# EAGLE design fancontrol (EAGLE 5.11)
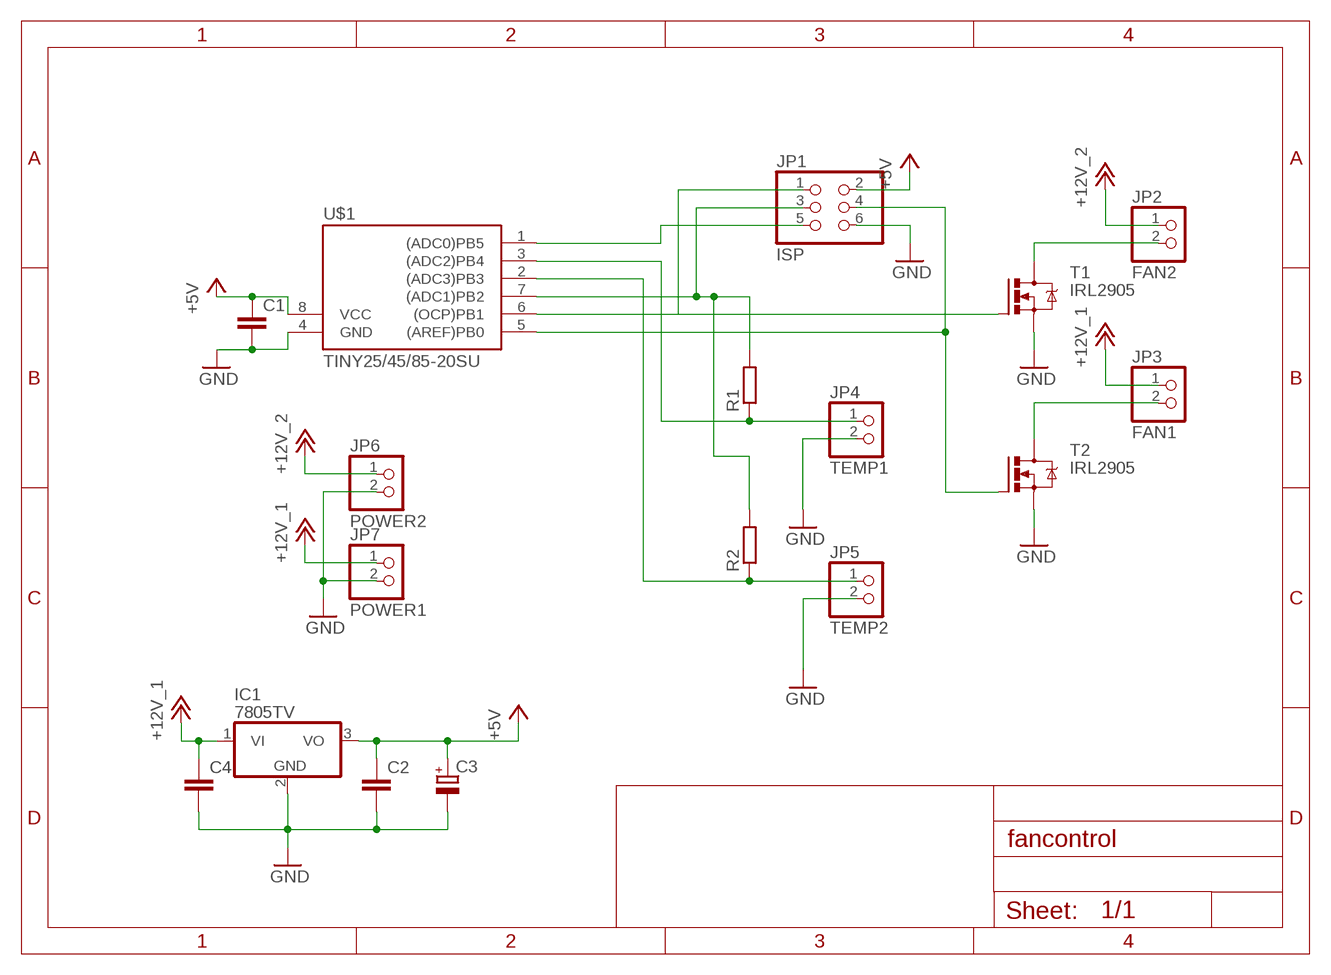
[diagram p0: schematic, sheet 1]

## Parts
C1  C-EU050-024X044  [C050-024X044]
C2  C-EU025-024X044  [C025-024X044]
C3  CPOL-EUE5-10.5  [E5-10,5]
C4  C-EU025-024X044  [C025-024X044]
IC1  7805TV  [TO220V]
JP1  ISP  PINHD-2X3  [2X03]
JP2  FAN2  PINHD-1X2  [1X02]
JP3  FAN1  PINHD-1X2  [1X02]
JP4  TEMP1  PINHD-1X2  [1X02]
JP5  TEMP2  PINHD-1X2  [1X02]
JP6  POWER2  PINHD-1X2  [1X02]
JP7  POWER1  PINHD-1X2  [1X02]
R1  R-EU_0207/2V  [0207/2V]
R2  R-EU_0207/2V  [0207/2V]
T1  IRL2905  [D-PAK_TO252AA]
T2  IRL2905  [D-PAK_TO252AA]
U$1  TINY25/45/85-20SU  [SOIC8]

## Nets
+5V: C1.1 C2.1 C3.+ IC1.3(VO) JP1.2 U$1.8(VCC)
+12V_1: C4.1 IC1.1(VI) JP3.1 JP7.1
+12V_2: JP2.1 JP6.1
GND: C1.2 C2.2 C3.- C4.2 IC1.2(GND) JP1.6 JP4.2 JP5.2 JP6.2 JP7.2 T1.3(S) T2.3(S) U$1.4(GND)
N$1: JP1.5 U$1.1((ADC0)PB5)
N$2: JP1.1 T1.1(G) U$1.6((OCP)PB1)
N$3: JP1.3 R1.2 R2.2 U$1.7((ADC1)PB2)
N$4: JP2.2 T1.4(D)
N$5: JP1.4 T2.1(G) U$1.5((AREF)PB0)
N$6: JP3.2 T2.4(D)
N$7: JP4.1 R1.1 U$1.3((ADC2)PB4)
N$8: JP5.1 R2.1 U$1.2((ADC3)PB3)

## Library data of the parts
C1 C2 C4 = rcl:C-EU: CAPACITOR, European symbol
C3 = rcl:CPOL-EU: POLARIZED CAPACITOR, European symbol
IC1 = linear:78*: Positive VOLTAGE REGULATOR Source: http://cache.national.com/ds/LM/LM78L05.pdf http://www.fairchildsemi.com/ds/LM/LM7805.pdf
JP1 = pinhead:PINHD-2X3: PIN HEADER
JP2-JP7 = pinhead:PINHD-1X2: PIN HEADER
R1 R2 = rcl:R-EU_: RESISTOR, European symbol
T1 T2 = transistor-power:IRL?2905: HEXFET® Power MOSFET VDSS = 55V RDS(on) = 0.027W ID = 42A Logic-Level Gate Drive Ultra Low On-Resistance Surface Mount (IRLR2905) Straight Lead (IRLU2905) Advanced Process Technology Fast Switching Fully Avalanche Rated www.irf.com
U$1 = avr-7:TINY25/45/85

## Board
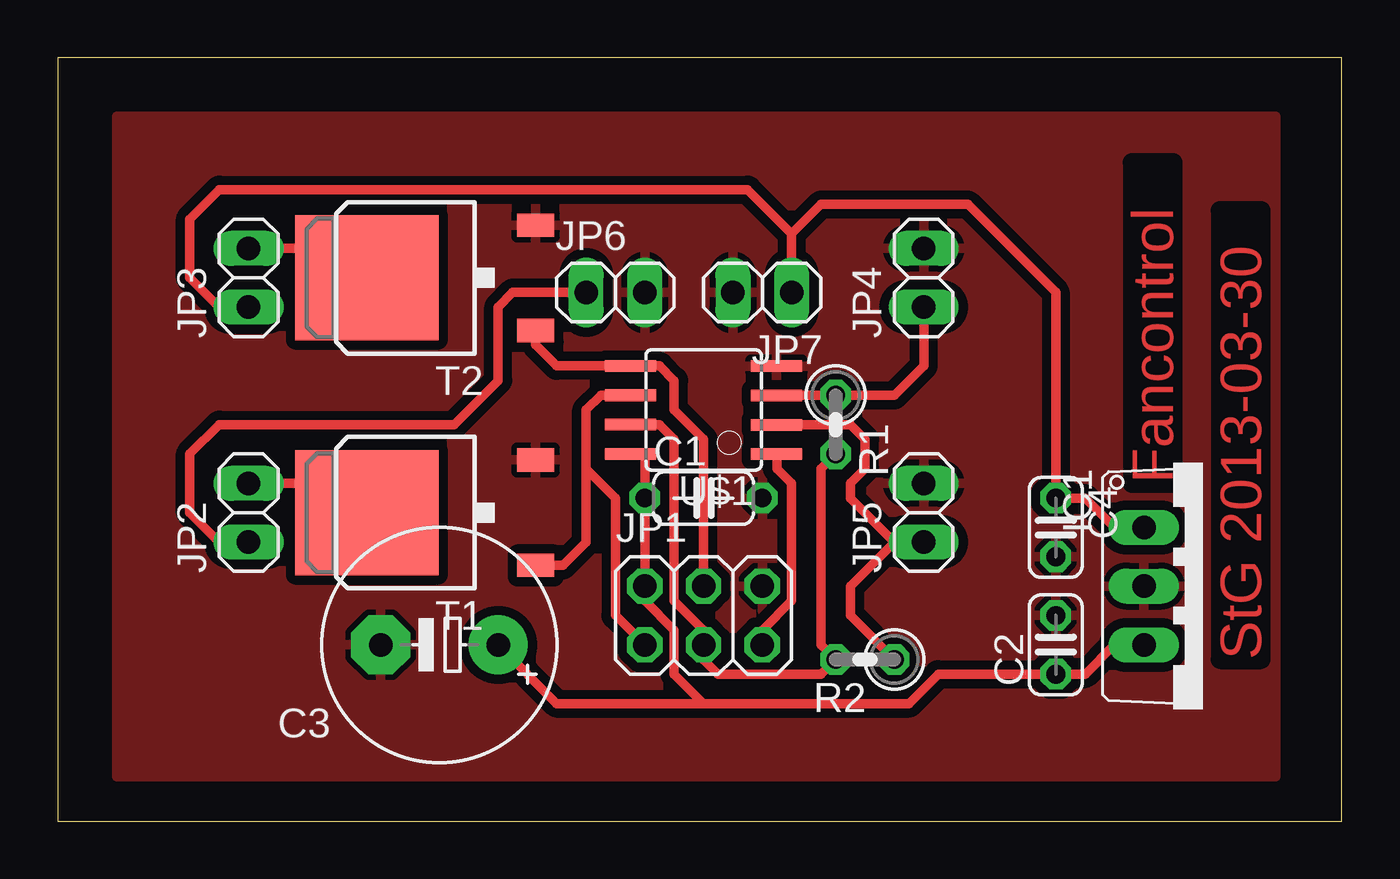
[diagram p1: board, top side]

Size 55.55 x 33.01 mm. Coordinates in mm from the lower left corner, seen from the top.
Outline: 0,0 55.55,0 55.55,33.01 0,33.01 0,0
Copper layers (1*16): Top 0.035mm / dielectric 1.5mm / Bottom 0.035mm
Design rules "default": minimum track width 10mil, minimum drill 24mil, track to track 8mil, track to pad 8mil, pad to pad 8mil, via to via 8mil, smd to smd 8mil, copper to edge 40mil, drill to drill 8mil, minimum pad ring 10mil, minimum via ring 8mil, stop-mask expansion 4mil, vias tented up to drill 0mil, thermal gap 10mil

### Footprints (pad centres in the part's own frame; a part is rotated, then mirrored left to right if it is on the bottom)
C050-024X044 = drill 0.813 octagon: 1 -2.54,0; 2 2.54,0
C025-024X044 = drill 0.813 octagon: 1 -1.27,0; 2 1.27,0
E5-10,5 = drill 1.016 pad 2.54 round: + -2.54,0 | drill 1.016 pad 2.54 octagon: - 2.54,0
TO220V = drill 1.016 long: 1 -2.54,-2.54; 2 0,-2.54; 3 2.54,-2.54
2X03 = drill 1.016 octagon: 1 -2.54,-1.27; 2 -2.54,1.27; 3 0,-1.27; 4 0,1.27; 5 2.54,-1.27; 6 2.54,1.27
1X02 = drill 1.016 long: 1 -1.27,0; 2 1.27,0
0207/2V = drill 0.813 octagon: 1 -1.27,0; 2 1.27,0
D-PAK_TO252AA = smd 1 x 1.6: 1 -2.28,-4.8; 3 2.28,-4.8 | smd 5.4 x 6.2: 4 0,2.5
SOIC8 = smd 0.5 x 2.2: 1 -1.905,-3.154; 2 -0.645,-3.154; 3 0.625,-3.154; 4 1.895,-3.154; 5 1.905,3.154; 6 0.635,3.154; 7 -0.635,3.154; 8 -1.905,3.154

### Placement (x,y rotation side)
C1  27.94,13.97 0 top
C2  43.18,7.62 90 top
C3  16.51,7.62 180 top
C4  43.18,12.7 270 top
IC1  49.53,10.16 270 top
JP1  27.94,8.89 0 top
JP2  8.26,13.34 90 top
JP3  8.26,23.5 90 top
JP4  37.47,23.5 90 top
JP5  37.47,13.34 90 top
JP6  24.13,22.86 0 top
JP7  30.48,22.86 180 top
R1  33.66,17.14 270 top
R2  34.92,6.99 180 top
T1  15.88,13.34 90 top
T2  15.88,23.5 90 top
U$1  27.94,17.78 90 top

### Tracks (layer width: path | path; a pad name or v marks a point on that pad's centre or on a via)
+5V
  Top 0.406: U$1.8 25.4,15.88 C1.1 JP1.2 25.4,9.53 26.67,8.26 26.67,6.35 27.94,5.08 | IC1.3 45.72,7.62 44.45,6.35 C2.1 38.1,6.35 36.83,5.08 27.94,5.08 | C3.+ 21.59,5.08 27.94,5.08
+12V_1
  Top 0.406: IC1.1 45.72,12.7 44.45,13.97 C4.1 43.18,22.86 39.37,26.67 33.02,26.67 31.75,25.4 | JP3.1 6.99,22.23 5.71,23.5 5.71,26.04 6.99,27.3 29.84,27.3 31.75,25.4 | 31.75,25.4 JP7.1
+12V_2
  Top 0.406: JP2.1 6.99,12.06 5.71,13.34 5.71,15.88 6.99,17.14 17.14,17.14 19.05,19.05 19.05,22.23 19.68,22.86 JP6.1
GND
  pour Top (isolate 0.406): 2.54,30.48 2.54,1.91 52.7,1.91 52.7,30.48
N$1
  Top 0.406: JP1.5 30.48,8.26 31.75,9.53 31.75,14.61 31.11,15.24 31.11,15.85 U$1.1
N$2
  Top 0.406: 22.86,15.24 22.86,17.78 23.5,18.41 U$1.6 | JP1.1 24.13,8.89 24.13,13.97 22.86,15.24 | 22.86,15.24 22.86,12.06 21.85,11.05 T1.1
N$3
  Top 0.406: U$1.7 26.04,17.14 26.67,16.51 26.67,9.53 27.94,8.26 JP1.3 27.94,6.99 28.57,6.35 33.02,6.35 R2.2 33.02,7.62 33.02,15.24 R1.2
N$4
  Top 0.406: JP2.2 13.38,14.61 T1.4
N$5
  Top 0.406: JP1.4 27.94,16.51 26.67,17.78 26.67,19.05 26.04,19.68 U$1.5 21.59,19.68 20.68,20.6 T2.1
N$6
  Top 0.406: JP3.2 13.38,24.77 T2.4
N$7
  Top 0.406: U$1.3 31.1,18.41 R1.1 36.2,18.41 37.47,19.68 JP4.1
N$8
  Top 0.406: U$1.2 34.3,17.14 34.92,16.51 34.92,15.24 34.29,14.61 34.29,13.97 36.2,12.06 | R2.1 34.29,8.89 34.29,10.16 36.2,12.06 | 36.2,12.06 JP5.1

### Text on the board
Top: Fancontrol | StG 2013-03-30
